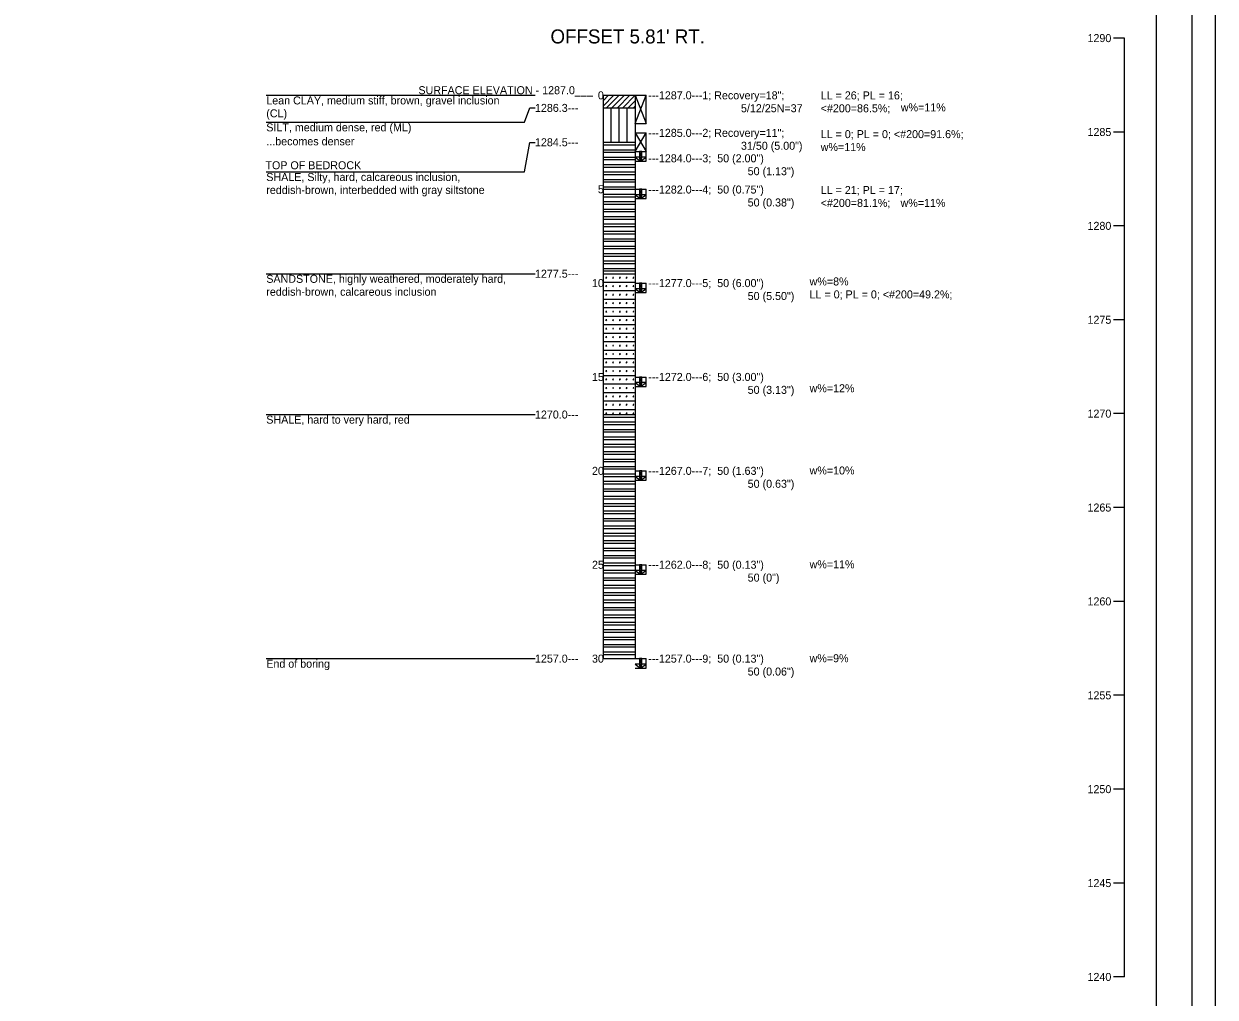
# Model space of a CAD drawing. Extents: x -6 to 173, y 24 to 64.
# Drawn here: x 65.85 to 84.3, y 35.64 to 50.71 of the extents above; entities that cross this region are included whole.
import ezdxf

# ---------------------------------------------------------------- set-up
doc = ezdxf.new("R2010")
doc.units = 0
for name, color, linetype in [('SHT_Plot_Shape_Full', 7, 'Continuous'), ('SHT_Plot_Shape_Half', 7, 'Continuous'), ('SHT_Sheet_Border', 7, 'Continuous')]:
    doc.layers.add(name, color=color, linetype=linetype)

msp = doc.modelspace()

# ---------------------------------------------------------------- linework, layer by layer
msp.add_line((82.895, 35.958), (82.895, 50.493))
for points in [[(82.895, 50.493), (82.729, 50.493)], [(69.603, 49.607), (73.77, 49.607)], [(74.819, 49.523), (74.902, 49.607)], [(74.819, 49.44), (74.985, 49.607)], [(74.819, 49.607), (74.819, 40.886)], [(74.819, 49.607), (75.319, 49.607)], [(74.874, 49.412), (75.069, 49.607)], [(74.957, 49.412), (75.152, 49.607)], [(75.041, 49.412), (75.235, 49.607)], [(75.124, 49.412), (75.319, 49.607)], [(75.207, 49.412), (75.319, 49.523)], [(75.319, 49.607), (75.485, 49.171)], [(75.319, 49.171), (75.485, 49.607)], [(75.319, 49.607), (75.485, 49.607)], [(75.319, 49.607), (75.319, 40.886)], [(75.485, 49.171), (75.485, 49.607)], [(69.603, 49.19), (73.603, 49.19), (73.687, 49.412), (73.77, 49.412)], [(74.819, 49.412), (75.319, 49.412)], [(74.944, 48.88), (74.944, 49.412)], [(75.069, 48.88), (75.069, 49.412)], [(75.194, 48.88), (75.194, 49.412)], [(75.291, 49.412), (75.319, 49.44)], [(75.319, 49.171), (75.485, 49.171)], [(75.319, 49.025), (75.485, 48.735)], [(75.319, 48.735), (75.485, 49.025)], [(75.319, 49.025), (75.485, 49.025)], [(75.485, 48.735), (75.485, 49.025)], [(82.895, 49.039), (82.729, 49.039)], [(69.603, 48.42), (69.77, 48.42), (73.603, 48.42), (73.687, 48.875), (73.77, 48.875)], [(74.819, 48.88), (75.319, 48.88)], [(74.819, 48.88), (75.319, 48.88)], [(74.819, 48.841), (75.319, 48.841)], [(74.819, 48.765), (75.319, 48.765)], [(74.819, 48.726), (75.319, 48.726)], [(75.319, 48.735), (75.485, 48.735)], [(75.319, 48.735), (75.485, 48.735)], [(75.485, 48.589), (75.485, 48.735)], [(74.819, 48.65), (75.319, 48.65)], [(74.819, 48.611), (75.319, 48.611)], [(74.819, 48.536), (75.319, 48.536)], [(75.319, 48.589), (75.485, 48.589)], [(74.819, 48.496), (75.319, 48.496)], [(74.819, 48.421), (75.319, 48.421)], [(74.819, 48.381), (75.319, 48.381)], [(74.819, 48.306), (75.319, 48.306)], [(74.819, 48.266), (75.319, 48.266)], [(74.819, 48.191), (75.319, 48.191)], [(74.819, 48.152), (75.319, 48.152)], [(74.819, 48.076), (75.319, 48.076)], [(74.819, 48.037), (75.319, 48.037)], [(75.319, 48.153), (75.485, 48.153)], [(75.319, 48.008), (75.485, 48.008)], [(75.485, 48.008), (75.485, 48.153)], [(74.819, 47.961), (75.319, 47.961)], [(74.819, 47.922), (75.319, 47.922)], [(74.819, 47.847), (75.319, 47.847)], [(74.819, 47.807), (75.319, 47.807)], [(74.819, 47.732), (75.319, 47.732)], [(74.819, 47.692), (75.319, 47.692)], [(74.819, 47.617), (75.319, 47.617)], [(74.819, 47.577), (75.319, 47.577)], [(74.819, 47.502), (75.319, 47.502)], [(74.819, 47.463), (75.319, 47.463)], [(82.895, 47.586), (82.729, 47.586)], [(74.819, 47.387), (75.319, 47.387)], [(74.819, 47.348), (75.319, 47.348)], [(74.819, 47.272), (75.319, 47.272)], [(74.819, 47.233), (75.319, 47.233)], [(74.819, 47.158), (75.319, 47.158)], [(74.819, 47.118), (75.319, 47.118)], [(74.819, 47.043), (75.319, 47.043)], [(74.819, 47.003), (75.319, 47.003)], [(74.819, 46.928), (75.319, 46.928)], [(74.819, 46.889), (75.319, 46.889)], [(69.603, 46.845), (73.77, 46.845)], [(74.819, 46.845), (75.319, 46.845)], [(74.819, 46.845), (75.319, 46.845)], [(74.819, 46.714), (75.319, 46.714)], [(75.319, 46.7), (75.485, 46.7)], [(75.485, 46.554), (75.485, 46.7)], [(74.819, 46.583), (75.319, 46.583)], [(75.319, 46.554), (75.485, 46.554)], [(74.819, 46.451), (75.319, 46.451)], [(74.819, 46.32), (75.319, 46.32)], [(74.819, 46.189), (75.319, 46.189)], [(74.819, 46.058), (75.319, 46.058)], [(82.895, 46.132), (82.729, 46.132)], [(74.819, 45.926), (75.319, 45.926)], [(74.819, 45.795), (75.319, 45.795)], [(74.819, 45.664), (75.319, 45.664)], [(74.819, 45.533), (75.319, 45.533)], [(74.819, 45.402), (75.319, 45.402)], [(74.819, 45.27), (75.319, 45.27)], [(75.319, 45.246), (75.485, 45.246)], [(75.485, 45.101), (75.485, 45.246)], [(74.819, 45.139), (75.319, 45.139)], [(75.319, 45.101), (75.485, 45.101)], [(74.819, 45.008), (75.319, 45.008)], [(74.819, 44.877), (75.319, 44.877)], [(69.603, 44.665), (73.77, 44.665)], [(74.819, 44.745), (75.319, 44.745)], [(74.819, 44.665), (75.319, 44.665)], [(74.819, 44.665), (75.319, 44.665)], [(82.895, 44.679), (82.729, 44.679)], [(74.819, 44.626), (75.319, 44.626)], [(74.819, 44.55), (75.319, 44.55)], [(74.819, 44.511), (75.319, 44.511)], [(74.819, 44.435), (75.319, 44.435)], [(74.819, 44.396), (75.319, 44.396)], [(74.819, 44.32), (75.319, 44.32)], [(74.819, 44.281), (75.319, 44.281)], [(74.819, 44.206), (75.319, 44.206)], [(74.819, 44.166), (75.319, 44.166)], [(74.819, 44.091), (75.319, 44.091)], [(74.819, 44.051), (75.319, 44.051)], [(74.819, 43.976), (75.319, 43.976)], [(74.819, 43.937), (75.319, 43.937)], [(74.819, 43.861), (75.319, 43.861)], [(74.819, 43.822), (75.319, 43.822)], [(74.819, 43.746), (75.319, 43.746)], [(75.319, 43.793), (75.485, 43.793)], [(75.485, 43.647), (75.485, 43.793)], [(74.819, 43.707), (75.319, 43.707)], [(74.819, 43.631), (75.319, 43.631)], [(74.819, 43.592), (75.319, 43.592)], [(75.319, 43.647), (75.485, 43.647)], [(74.819, 43.517), (75.319, 43.517)], [(74.819, 43.477), (75.319, 43.477)], [(74.819, 43.402), (75.319, 43.402)], [(74.819, 43.362), (75.319, 43.362)], [(74.819, 43.287), (75.319, 43.287)], [(74.819, 43.248), (75.319, 43.248)], [(82.895, 43.225), (82.729, 43.225)], [(74.819, 43.172), (75.319, 43.172)], [(74.819, 43.133), (75.319, 43.133)], [(74.819, 43.057), (75.319, 43.057)], [(74.819, 43.018), (75.319, 43.018)], [(74.819, 42.942), (75.319, 42.942)], [(74.819, 42.903), (75.319, 42.903)], [(74.819, 42.828), (75.319, 42.828)], [(74.819, 42.788), (75.319, 42.788)], [(74.819, 42.713), (75.319, 42.713)], [(74.819, 42.673), (75.319, 42.673)], [(74.819, 42.598), (75.319, 42.598)], [(74.819, 42.559), (75.319, 42.559)], [(74.819, 42.483), (75.319, 42.483)], [(74.819, 42.444), (75.319, 42.444)], [(74.819, 42.368), (75.319, 42.368)], [(74.819, 42.329), (75.319, 42.329)], [(75.319, 42.339), (75.485, 42.339)], [(75.485, 42.194), (75.485, 42.339)], [(74.819, 42.253), (75.319, 42.253)], [(74.819, 42.214), (75.319, 42.214)], [(74.819, 42.139), (75.319, 42.139)], [(74.819, 42.099), (75.319, 42.099)], [(75.319, 42.194), (75.485, 42.194)], [(74.819, 42.024), (75.319, 42.024)], [(74.819, 41.984), (75.319, 41.984)], [(74.819, 41.909), (75.319, 41.909)], [(74.819, 41.87), (75.319, 41.87)], [(74.819, 41.794), (75.319, 41.794)], [(74.819, 41.755), (75.319, 41.755)], [(82.895, 41.772), (82.729, 41.772)], [(74.819, 41.679), (75.319, 41.679)], [(74.819, 41.64), (75.319, 41.64)], [(74.819, 41.564), (75.319, 41.564)], [(74.819, 41.525), (75.319, 41.525)], [(74.819, 41.45), (75.319, 41.45)], [(74.819, 41.41), (75.319, 41.41)], [(74.819, 41.335), (75.319, 41.335)], [(74.819, 41.295), (75.319, 41.295)], [(74.819, 41.22), (75.319, 41.22)], [(74.819, 41.181), (75.319, 41.181)], [(74.819, 41.105), (75.319, 41.105)], [(74.819, 41.066), (75.319, 41.066)], [(74.819, 40.99), (75.319, 40.99)], [(69.603, 40.886), (73.77, 40.886)], [(74.819, 40.951), (75.319, 40.951)], [(74.819, 40.886), (75.319, 40.886)], [(75.319, 40.886), (75.485, 40.886)], [(75.485, 40.74), (75.485, 40.886)], [(75.319, 40.74), (75.485, 40.74)], [(82.895, 40.318), (82.729, 40.318)], [(82.895, 38.865), (82.729, 38.865)], [(82.895, 37.411), (82.729, 37.411)], [(82.895, 35.958), (82.729, 35.958)]]:
    msp.add_lwpolyline(points)
for points in [[(75.385, 48.647), (75.419, 48.647), (75.419, 48.735), (75.385, 48.647)], [(75.385, 48.647), (75.419, 48.735), (75.385, 48.735), (75.385, 48.647)], [(75.385, 48.647), (75.319, 48.647), (75.402, 48.589), (75.385, 48.647)], [(75.385, 48.647), (75.402, 48.589), (75.419, 48.647), (75.385, 48.647)], [(75.402, 48.589), (75.485, 48.647), (75.419, 48.647), (75.402, 48.589)], [(75.385, 48.066), (75.319, 48.066), (75.402, 48.008), (75.385, 48.066)], [(75.385, 48.066), (75.419, 48.066), (75.419, 48.153), (75.385, 48.066)], [(75.385, 48.066), (75.419, 48.153), (75.385, 48.153), (75.385, 48.066)], [(75.385, 48.066), (75.402, 48.008), (75.419, 48.066), (75.385, 48.066)], [(75.402, 48.008), (75.485, 48.066), (75.419, 48.066), (75.402, 48.008)], [(74.865, 46.773), (74.878, 46.786), (74.865, 46.786), (74.865, 46.773)], [(74.97, 46.773), (74.983, 46.786), (74.97, 46.786), (74.97, 46.773)], [(75.075, 46.773), (75.088, 46.786), (75.075, 46.786), (75.075, 46.773)], [(75.18, 46.773), (75.193, 46.786), (75.18, 46.786), (75.18, 46.773)], [(75.285, 46.773), (75.298, 46.786), (75.285, 46.786), (75.285, 46.773)], [(75.385, 46.613), (75.419, 46.613), (75.419, 46.7), (75.385, 46.613)], [(75.385, 46.613), (75.419, 46.7), (75.385, 46.7), (75.385, 46.613)], [(74.865, 46.642), (74.878, 46.655), (74.865, 46.655), (74.865, 46.642)], [(74.865, 46.51), (74.878, 46.524), (74.865, 46.524), (74.865, 46.51)], [(74.97, 46.642), (74.983, 46.655), (74.97, 46.655), (74.97, 46.642)], [(74.97, 46.51), (74.983, 46.524), (74.97, 46.524), (74.97, 46.51)], [(75.075, 46.642), (75.088, 46.655), (75.075, 46.655), (75.075, 46.642)], [(75.075, 46.51), (75.088, 46.524), (75.075, 46.524), (75.075, 46.51)], [(75.18, 46.642), (75.193, 46.655), (75.18, 46.655), (75.18, 46.642)], [(75.18, 46.51), (75.193, 46.524), (75.18, 46.524), (75.18, 46.51)], [(75.285, 46.642), (75.298, 46.655), (75.285, 46.655), (75.285, 46.642)], [(75.285, 46.51), (75.298, 46.524), (75.285, 46.524), (75.285, 46.51)], [(75.385, 46.613), (75.319, 46.613), (75.402, 46.554), (75.385, 46.613)], [(75.385, 46.613), (75.402, 46.554), (75.419, 46.613), (75.385, 46.613)], [(75.402, 46.554), (75.485, 46.613), (75.419, 46.613), (75.402, 46.554)], [(74.865, 46.379), (74.878, 46.392), (74.865, 46.392), (74.865, 46.379)], [(74.97, 46.379), (74.983, 46.392), (74.97, 46.392), (74.97, 46.379)], [(75.075, 46.379), (75.088, 46.392), (75.075, 46.392), (75.075, 46.379)], [(75.18, 46.379), (75.193, 46.392), (75.18, 46.392), (75.18, 46.379)], [(75.285, 46.379), (75.298, 46.392), (75.285, 46.392), (75.285, 46.379)], [(74.865, 46.248), (74.878, 46.261), (74.865, 46.261), (74.865, 46.248)], [(74.97, 46.248), (74.983, 46.261), (74.97, 46.261), (74.97, 46.248)], [(75.075, 46.248), (75.088, 46.261), (75.075, 46.261), (75.075, 46.248)], [(75.18, 46.248), (75.193, 46.261), (75.18, 46.261), (75.18, 46.248)], [(75.285, 46.248), (75.298, 46.261), (75.285, 46.261), (75.285, 46.248)], [(74.865, 46.117), (74.878, 46.13), (74.865, 46.13), (74.865, 46.117)], [(74.865, 45.986), (74.878, 45.999), (74.865, 45.999), (74.865, 45.986)], [(74.97, 46.117), (74.983, 46.13), (74.97, 46.13), (74.97, 46.117)], [(74.97, 45.986), (74.983, 45.999), (74.97, 45.999), (74.97, 45.986)], [(75.075, 46.117), (75.088, 46.13), (75.075, 46.13), (75.075, 46.117)], [(75.075, 45.986), (75.088, 45.999), (75.075, 45.999), (75.075, 45.986)], [(75.18, 46.117), (75.193, 46.13), (75.18, 46.13), (75.18, 46.117)], [(75.18, 45.986), (75.193, 45.999), (75.18, 45.999), (75.18, 45.986)], [(75.285, 46.117), (75.298, 46.13), (75.285, 46.13), (75.285, 46.117)], [(75.285, 45.986), (75.298, 45.999), (75.285, 45.999), (75.285, 45.986)], [(74.865, 45.854), (74.878, 45.867), (74.865, 45.867), (74.865, 45.854)], [(74.97, 45.854), (74.983, 45.867), (74.97, 45.867), (74.97, 45.854)], [(75.075, 45.854), (75.088, 45.867), (75.075, 45.867), (75.075, 45.854)], [(75.18, 45.854), (75.193, 45.867), (75.18, 45.867), (75.18, 45.854)], [(75.285, 45.854), (75.298, 45.867), (75.285, 45.867), (75.285, 45.854)], [(74.865, 45.723), (74.878, 45.736), (74.865, 45.736), (74.865, 45.723)], [(74.865, 45.592), (74.878, 45.605), (74.865, 45.605), (74.865, 45.592)], [(74.97, 45.723), (74.983, 45.736), (74.97, 45.736), (74.97, 45.723)], [(74.97, 45.592), (74.983, 45.605), (74.97, 45.605), (74.97, 45.592)], [(75.075, 45.723), (75.088, 45.736), (75.075, 45.736), (75.075, 45.723)], [(75.075, 45.592), (75.088, 45.605), (75.075, 45.605), (75.075, 45.592)], [(75.18, 45.723), (75.193, 45.736), (75.18, 45.736), (75.18, 45.723)], [(75.18, 45.592), (75.193, 45.605), (75.18, 45.605), (75.18, 45.592)], [(75.285, 45.723), (75.298, 45.736), (75.285, 45.736), (75.285, 45.723)], [(75.285, 45.592), (75.298, 45.605), (75.285, 45.605), (75.285, 45.592)], [(74.865, 45.461), (74.878, 45.474), (74.865, 45.474), (74.865, 45.461)], [(74.97, 45.461), (74.983, 45.474), (74.97, 45.474), (74.97, 45.461)], [(75.075, 45.461), (75.088, 45.474), (75.075, 45.474), (75.075, 45.461)], [(75.18, 45.461), (75.193, 45.474), (75.18, 45.474), (75.18, 45.461)], [(75.285, 45.461), (75.298, 45.474), (75.285, 45.474), (75.285, 45.461)], [(74.865, 45.329), (74.878, 45.342), (74.865, 45.342), (74.865, 45.329)], [(74.97, 45.329), (74.983, 45.342), (74.97, 45.342), (74.97, 45.329)], [(75.075, 45.329), (75.088, 45.342), (75.075, 45.342), (75.075, 45.329)], [(75.18, 45.329), (75.193, 45.342), (75.18, 45.342), (75.18, 45.329)], [(75.285, 45.329), (75.298, 45.342), (75.285, 45.342), (75.285, 45.329)], [(75.385, 45.159), (75.419, 45.159), (75.419, 45.246), (75.385, 45.159)], [(75.385, 45.159), (75.419, 45.246), (75.385, 45.246), (75.385, 45.159)], [(74.865, 45.198), (74.878, 45.211), (74.865, 45.211), (74.865, 45.198)], [(74.865, 45.067), (74.878, 45.08), (74.865, 45.08), (74.865, 45.067)], [(74.97, 45.198), (74.983, 45.211), (74.97, 45.211), (74.97, 45.198)], [(74.97, 45.067), (74.983, 45.08), (74.97, 45.08), (74.97, 45.067)], [(75.075, 45.198), (75.088, 45.211), (75.075, 45.211), (75.075, 45.198)], [(75.075, 45.067), (75.088, 45.08), (75.075, 45.08), (75.075, 45.067)], [(75.18, 45.198), (75.193, 45.211), (75.18, 45.211), (75.18, 45.198)], [(75.18, 45.067), (75.193, 45.08), (75.18, 45.08), (75.18, 45.067)], [(75.285, 45.198), (75.298, 45.211), (75.285, 45.211), (75.285, 45.198)], [(75.285, 45.067), (75.298, 45.08), (75.285, 45.08), (75.285, 45.067)], [(75.385, 45.159), (75.319, 45.159), (75.402, 45.101), (75.385, 45.159)], [(75.385, 45.159), (75.402, 45.101), (75.419, 45.159), (75.385, 45.159)], [(75.402, 45.101), (75.485, 45.159), (75.419, 45.159), (75.402, 45.101)], [(74.865, 44.936), (74.878, 44.949), (74.865, 44.949), (74.865, 44.936)], [(74.97, 44.936), (74.983, 44.949), (74.97, 44.949), (74.97, 44.936)], [(75.075, 44.936), (75.088, 44.949), (75.075, 44.949), (75.075, 44.936)], [(75.18, 44.936), (75.193, 44.949), (75.18, 44.949), (75.18, 44.936)], [(75.285, 44.936), (75.298, 44.949), (75.285, 44.949), (75.285, 44.936)], [(74.865, 44.804), (74.878, 44.818), (74.865, 44.818), (74.865, 44.804)], [(74.865, 44.673), (74.878, 44.686), (74.865, 44.686), (74.865, 44.673)], [(74.97, 44.804), (74.983, 44.818), (74.97, 44.818), (74.97, 44.804)], [(74.97, 44.673), (74.983, 44.686), (74.97, 44.686), (74.97, 44.673)], [(75.075, 44.804), (75.088, 44.818), (75.075, 44.818), (75.075, 44.804)], [(75.075, 44.673), (75.088, 44.686), (75.075, 44.686), (75.075, 44.673)], [(75.18, 44.804), (75.193, 44.818), (75.18, 44.818), (75.18, 44.804)], [(75.18, 44.673), (75.193, 44.686), (75.18, 44.686), (75.18, 44.673)], [(75.285, 44.804), (75.298, 44.818), (75.285, 44.818), (75.285, 44.804)], [(75.285, 44.673), (75.298, 44.686), (75.285, 44.686), (75.285, 44.673)], [(75.385, 43.706), (75.419, 43.706), (75.419, 43.793), (75.385, 43.706)], [(75.385, 43.706), (75.419, 43.793), (75.385, 43.793), (75.385, 43.706)], [(75.385, 43.706), (75.319, 43.706), (75.402, 43.647), (75.385, 43.706)], [(75.385, 43.706), (75.402, 43.647), (75.419, 43.706), (75.385, 43.706)], [(75.402, 43.647), (75.485, 43.706), (75.419, 43.706), (75.402, 43.647)], [(75.385, 42.252), (75.419, 42.252), (75.419, 42.339), (75.385, 42.252)], [(75.385, 42.252), (75.419, 42.339), (75.385, 42.339), (75.385, 42.252)], [(75.385, 42.252), (75.319, 42.252), (75.402, 42.194), (75.385, 42.252)], [(75.385, 42.252), (75.402, 42.194), (75.419, 42.252), (75.385, 42.252)], [(75.402, 42.194), (75.485, 42.252), (75.419, 42.252), (75.402, 42.194)], [(75.385, 40.799), (75.319, 40.799), (75.402, 40.74), (75.385, 40.799)], [(75.385, 40.799), (75.419, 40.799), (75.419, 40.886), (75.385, 40.799)], [(75.385, 40.799), (75.419, 40.886), (75.385, 40.886), (75.385, 40.799)], [(75.385, 40.799), (75.402, 40.74), (75.419, 40.799), (75.385, 40.799)], [(75.402, 40.74), (75.485, 40.799), (75.419, 40.799), (75.402, 40.74)]]:
    msp.add_lwpolyline(points, close=True)
at = {"layer": 'SHT_Plot_Shape_Full'}
msp.add_lwpolyline([(48.302, 53.971), (84.302, 53.971), (84.302, 29.971), (48.302, 29.971)], close=True, dxfattribs=at)
at = {"layer": 'SHT_Plot_Shape_Half'}
msp.add_lwpolyline([(49.939, 53.146), (83.939, 53.146), (83.939, 31.146), (49.939, 31.146)], close=True, dxfattribs=at)
at = {"layer": 'SHT_Sheet_Border'}
msp.add_lwpolyline([(51.889, 52.646), (83.389, 52.646), (83.389, 31.646), (51.889, 31.646)], close=True, dxfattribs=at)

# ---------------------------------------------------------------- texts
for s, height, p in [("OFFSET 5.81' RT.", 0.217, (74.005, 50.41)), ('1290', 0.124, (82.324, 50.431)), ('SURFACE ELEVATION - 1287.0___', 0.124, (71.96, 49.624)), ('0', 0.124, (74.74, 49.545)), ('---1287.0---1; Recovery=18";', 0.124, (75.519, 49.545)), ('LL = 26; PL = 16;', 0.124, (78.191, 49.544)), ('Lean CLAY, medium stiff, brown, gravel inclusion', 0.124, (69.603, 49.466)), ('1286.3---', 0.124, (73.765, 49.35)), ('5/12/25N=37', 0.124, (76.956, 49.345)), ('<#200=86.5%;', 0.124, (78.191, 49.344)), ('w%=11%', 0.124, (79.432, 49.358)), ('(CL)', 0.124, (69.603, 49.266)), ('SILT, medium dense, red (ML)', 0.124, (69.603, 49.049)), ('---1285.0---2; Recovery=11";', 0.124, (75.519, 48.964)), ('1285', 0.124, (82.324, 48.977)), ('...becomes denser', 0.124, (69.603, 48.833)), ('1284.5---', 0.124, (73.765, 48.818)), ('LL = 0; PL = 0; <#200=91.6%;', 0.124, (78.191, 48.944)), ('31/50 (5.00")', 0.124, (76.956, 48.764)), ('w%=11%', 0.124, (78.191, 48.744)), ('TOP OF BEDROCK', 0.124, (69.59, 48.462)), ('---1284.0---3;  50 (2.00")', 0.124, (75.519, 48.57)), ('SHALE, Silty, hard, calcareous inclusion,', 0.124, (69.603, 48.28)), ('50 (1.13")', 0.124, (77.06, 48.37)), ('reddish-brown, interbedded with gray siltstone', 0.124, (69.603, 48.08)), ('5', 0.124, (74.74, 48.091)), ('---1282.0---4;  50 (0.75")', 0.124, (75.519, 48.086)), ('LL = 21; PL = 17;', 0.124, (78.191, 48.079)), ('50 (0.38")', 0.124, (77.06, 47.886)), ('<#200=81.1%;', 0.124, (78.191, 47.879)), ('w%=11%', 0.124, (79.428, 47.88)), ('1280', 0.124, (82.324, 47.524)), ('1277.5---', 0.124, (73.765, 46.783)), ('SANDSTONE, highly weathered, moderately hard,', 0.124, (69.603, 46.704)), ('10', 0.124, (74.648, 46.638)), ('---1277.0---5;  50 (6.00")', 0.124, (75.519, 46.638)), ('w%=8%', 0.124, (78.019, 46.663)), ('reddish-brown, calcareous inclusion', 0.124, (69.603, 46.504)), ('50 (5.50")', 0.124, (77.06, 46.438)), ('LL = 0; PL = 0; <#200=49.2%;', 0.124, (78.019, 46.463)), ('1275', 0.124, (82.324, 46.07)), ('15', 0.124, (74.648, 45.184)), ('---1272.0---6;  50 (3.00")', 0.124, (75.519, 45.185)), ('50 (3.13")', 0.124, (77.06, 44.985)), ('w%=12%', 0.124, (78.019, 45.01)), ('1270.0---', 0.124, (73.765, 44.603)), ('1270', 0.124, (82.324, 44.617)), ('SHALE, hard to very hard, red', 0.124, (69.603, 44.524)), ('20', 0.124, (74.648, 43.731)), ('---1267.0---7;  50 (1.63")', 0.124, (75.519, 43.731)), ('w%=10%', 0.124, (78.019, 43.737)), ('50 (0.63")', 0.124, (77.06, 43.531)), ('1265', 0.124, (82.324, 43.163)), ('25', 0.124, (74.648, 42.277)), ('---1262.0---8;  50 (0.13")', 0.124, (75.519, 42.278)), ('w%=11%', 0.124, (78.019, 42.284)), ('50 (0")', 0.124, (77.06, 42.078)), ('1260', 0.124, (82.324, 41.71)), ('End of boring', 0.124, (69.603, 40.745)), ('1257.0---', 0.124, (73.765, 40.824)), ('30', 0.124, (74.648, 40.824)), ('---1257.0---9;  50 (0.13")', 0.124, (75.519, 40.824)), ('w%=9%', 0.124, (78.019, 40.83)), ('50 (0.06")', 0.124, (77.06, 40.624)), ('1255', 0.124, (82.324, 40.256)), ('1250', 0.124, (82.324, 38.803)), ('1245', 0.124, (82.324, 37.349)), ('1240', 0.124, (82.324, 35.896))]:
    msp.add_text(s, height=height).set_placement(p)

doc.saveas('drawing.dxf')
